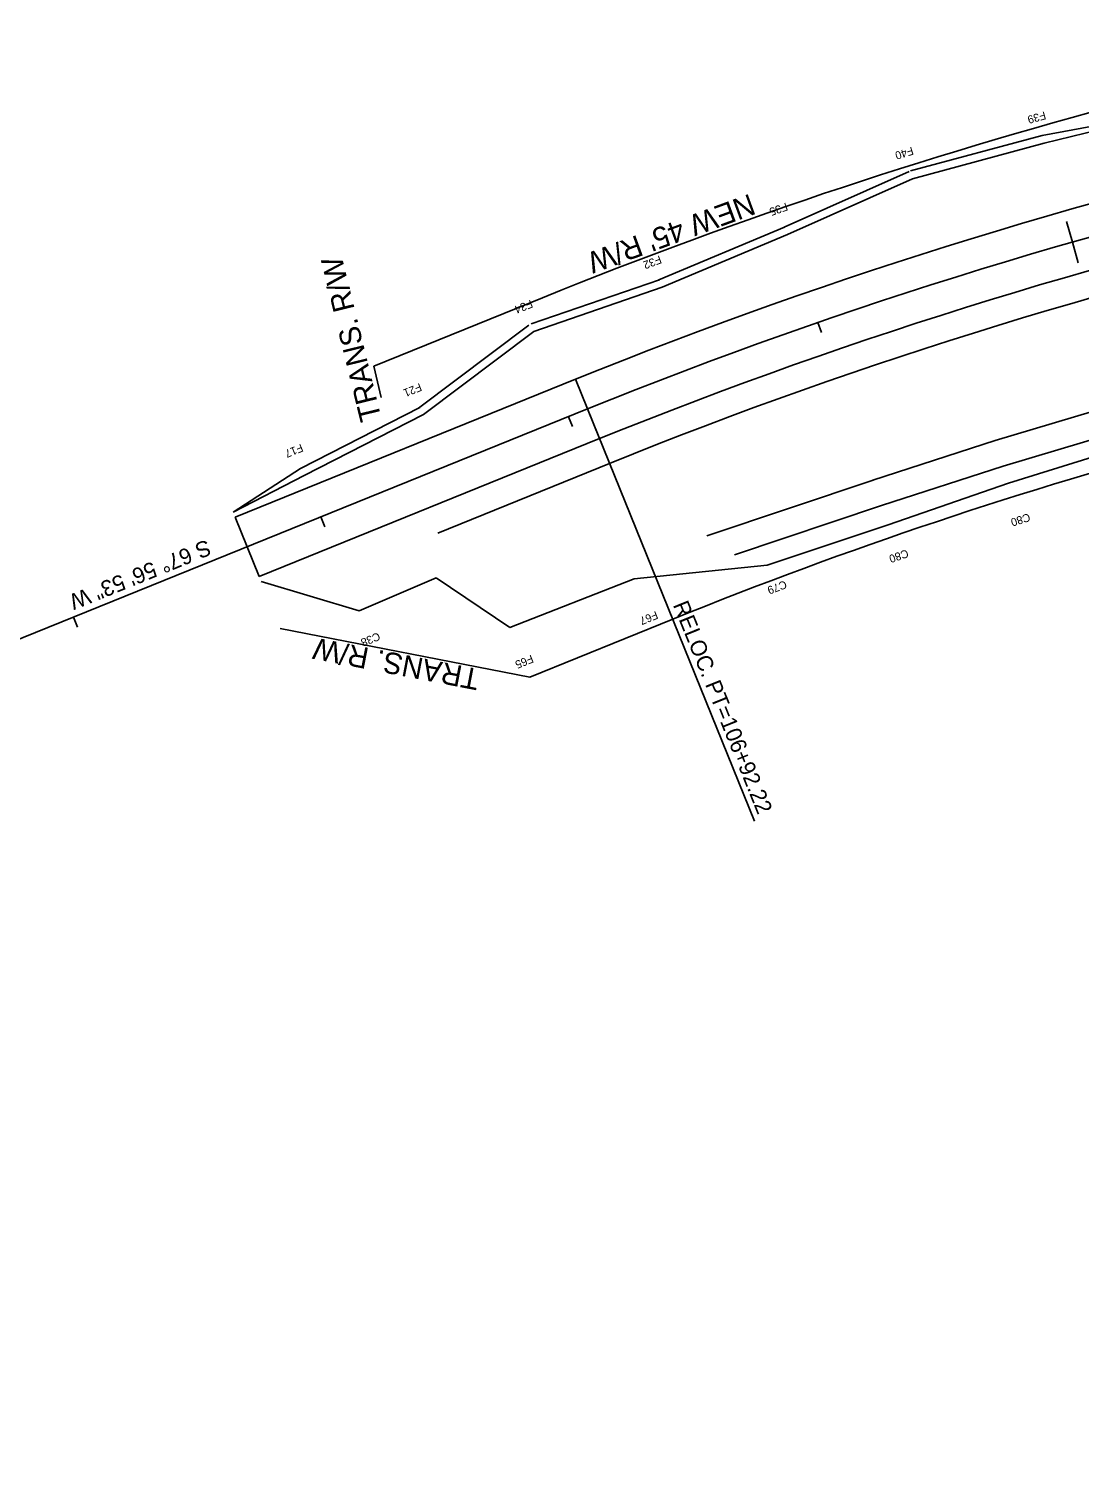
# Model space of a CAD drawing. Extents: x 1475170 to 1480100, y 1103245 to 1119475.
# Drawn here: x 1475960 to 1476354, y 1110763 to 1111307 of the extents above; entities that cross this region are included whole.
import ezdxf

# ---------------------------------------------------------------- set-up
doc = ezdxf.new("R2010")
doc.units = 0
for name, color, linetype in [('RD_HC_CL_Rel', 7, 'Continuous'), ('RD_HC_Data_Rel', 7, 'Continuous'), ('RD_HC_Data_Tic_Rel', 7, 'Continuous'), ('RD_PD_CstnLmt', 7, 'Continuous'), ('RD_PD_CstnLmt_TX', 7, 'Continuous'), ('RD_PD_DR_Ditch', 7, 'Continuous'), ('RD_PD_DR_ErosCtrl', 7, 'Continuous'), ('RD_PD_Final_TrvlWay', 7, 'Continuous'), ('RD_PD_GR', 7, 'Continuous'), ('RD_PD_RW', 7, 'Continuous'), ('RD_PD_RW_TX', 7, 'Continuous')]:
    doc.layers.add(name, color=color, linetype=linetype)

msp = doc.modelspace()

# ---------------------------------------------------------------- linework, layer by layer
at = {"layer": 'RD_HC_CL_Rel'}
msp.add_line((1476169.52, 1111164.6), (1475177.73, 1110762.84), dxfattribs=at)
msp.add_arc((1476845.33, 1109496.28), 1800, 92.16, 112.05197, dxfattribs=at)
at = {"layer": 'RD_HC_Data_Rel'}
msp.add_line((1476169.52, 1111164.6), (1476232.12, 1111010.07), dxfattribs=at)
at = {"layer": 'RD_HC_Data_Tic_Rel'}
for p, q in [((1476351.2, 1111227.13), (1476349, 1111234.82)), ((1476351.2, 1111227.13), (1476353.39, 1111219.43)), ((1476255.85, 1111197.02), (1476257.16, 1111193.24)), ((1476162.32, 1111161.68), (1476163.82, 1111157.97)), ((1476069.63, 1111124.13), (1476071.13, 1111120.43)), ((1475976.95, 1111086.59), (1475978.45, 1111082.88))]:
    msp.add_line(p, q, dxfattribs=at)
at = {"layer": 'RD_PD_CstnLmt'}
for p, q in [((1476390.22, 1111276.33), (1476340.61, 1111264.19)), ((1476340.61, 1111264.19), (1476291.26, 1111250.91)), ((1476291.26, 1111250.91), (1476244.42, 1111230.01)), ((1476244.42, 1111230.01), (1476197.42, 1111210.21)), ((1476197.42, 1111210.21), (1476149.36, 1111193.65)), ((1476149.36, 1111193.65), (1476108.03, 1111162.52)), ((1476372.91, 1111151.08), (1476327.28, 1111136.83)), ((1476327.28, 1111136.83), (1476282.12, 1111121.22)), ((1476282.12, 1111121.22), (1476236.79, 1111106.05)), ((1476236.79, 1111106.05), (1476186.95, 1111100.88)), ((1476140.38, 1111082.66), (1476112.8, 1111101.37)), ((1476186.95, 1111100.88), (1476140.38, 1111082.66))]:
    msp.add_line(p, q, dxfattribs=at)
for points in [[(1476108.03, 1111162.52), (1476063.34, 1111139.68), (1476036.74, 1111125.91)], [(1476112.8, 1111101.37), (1476083.91, 1111088.89), (1476047.25, 1111099.96)]]:
    msp.add_lwpolyline(points, dxfattribs=at)
at = {"layer": 'RD_PD_DR_Ditch'}
for p, q in [((1476368.48, 1111166.58), (1476322.26, 1111152.73)), ((1476371.23, 1111156.97), (1476325.27, 1111143.19)), ((1476322.26, 1111152.73), (1476276.35, 1111137.87)), ((1476325.27, 1111143.19), (1476279.63, 1111128.42)), ((1476276.53, 1111137.93), (1476214.18, 1111117.08)), ((1476279.7, 1111128.45), (1476224.53, 1111109.99))]:
    msp.add_line(p, q, dxfattribs=at)
at = {"layer": 'RD_PD_DR_ErosCtrl'}
for p, q in [((1476390.22, 1111276.33), (1476339.9, 1111267.11)), ((1476339.84, 1111267.09), (1476290.48, 1111253.81)), ((1476290.04, 1111253.65), (1476243.19, 1111232.74)), ((1476243.25, 1111232.77), (1476196.25, 1111212.98)), ((1476196.44, 1111213.05), (1476148.39, 1111196.49)), ((1476147.56, 1111196.05), (1476106.22, 1111164.92))]:
    msp.add_line(p, q, dxfattribs=at)
msp.add_lwpolyline([(1476106.66, 1111165.19), (1476061.96, 1111142.34), (1476036.74, 1111125.91)], dxfattribs=at)
at = {"layer": 'RD_PD_Final_TrvlWay'}
for p, q in [((1476165.02, 1111175.72), (1476037.49, 1111124.06)), ((1476174.03, 1111153.48), (1476165.02, 1111175.72)), ((1476174.03, 1111153.48), (1476046.5, 1111101.82)), ((1476046.5, 1111101.82), (1476037.49, 1111124.06))]:
    msp.add_line(p, q, dxfattribs=at)
for radius in [1812, 1788]:
    msp.add_arc((1476845.33, 1109496.28), radius, 92.16, 112.05197, dxfattribs=at)
at = {"layer": 'RD_PD_GR'}
msp.add_line((1476177.78, 1111144.21), (1476113.37, 1111118.11), dxfattribs=at)
msp.add_arc((1476845.33, 1109496.28), 1778, 92.16, 112.05197, dxfattribs=at)
at = {"layer": 'RD_PD_RW'}
for p, q in [((1476152.63, 1111206.31), (1476089.4, 1111180.69)), ((1476089.4, 1111180.69), (1476092.14, 1111168.86)), ((1476147.89, 1111064.12), (1476054.38, 1111082.35)), ((1476201.44, 1111085.82), (1476147.89, 1111064.12))]:
    msp.add_line(p, q, dxfattribs=at)
for radius, start in [(1845, 104.60849), (1715, 97.97556)]:
    msp.add_arc((1476845.33, 1109496.28), radius, start, 112.05197, dxfattribs=at)

# ---------------------------------------------------------------- texts
at = {"layer": 'RD_HC_Data_Rel'}
for s, rotation, p in [('S 67%%d 56\' 53" W', 202.052, (1476026.86, 1111115.84)), ('RELOC. PT=106+92.22', 292.052, (1476201.41, 1111091.2))]:
    msp.add_text(s, height=6, rotation=rotation, dxfattribs=at).set_placement(p)
at = {"layer": 'RD_PD_CstnLmt_TX'}
for s, rotation, p in [('F39', 195.9333, (1476340.75, 1111276.19)), ('F40', 197.5249, (1476291.06, 1111262.91)), ('F35', 199.1164, (1476243.89, 1111241.99)), ('F32', 200.708, (1476196.53, 1111222.17)), ('F34', 202.052, (1476148.22, 1111205.6)), ('F21', 202.052, (1476106.62, 1111174.36)), ('F17', 202.052, (1476062.17, 1111151.61)), ('C80', 197.5249, (1476334.83, 1111125.58)), ('C80', 199.1164, (1476289.15, 1111112.06)), ('C79', 200.708, (1476243.47, 1111100.43)), ('F67', 202.052, (1476195.14, 1111088.95)), ('C38', 202.052, (1476091.05, 1111080.99)), ('F65', 202.052, (1476148.48, 1111072.54))]:
    msp.add_text(s, height=3, rotation=rotation, dxfattribs=at).set_placement(p)
at = {"layer": 'RD_PD_RW_TX'}
for s, rotation, p in [("NEW 45' R/W", 200.1597, (1476230.35, 1111245.4)), ('TRANS. R/W', 103.7604, (1476092.33, 1111161.07)), ('TRANS. R/W', 169.1129, (1476129.49, 1111067))]:
    msp.add_text(s, height=8, rotation=rotation, dxfattribs=at).set_placement(p)

doc.saveas('drawing.dxf')
